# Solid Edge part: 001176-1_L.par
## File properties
Last saved by: morva
Revision: 82
Accuracy: 0.990
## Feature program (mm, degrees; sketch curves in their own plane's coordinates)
body "unnamed Body 1"
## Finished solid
Body 1: solid body, 167 faces, 451 edges, 288 vertices.
  Faces by surface: cylinder 75, plane 50, torus 21, spline 10, cone 7, spun 4
  Edges by curve: line 182, circle 153, spline 65, curve on surface 51
Bounding box of the edges (mm; curved faces can reach further): 94.424 x 55.613 x 60.053, from (457.2918, 400.3153, -108.0376) to (551.716, 455.9287, -47.9843).
Cylindrical faces by radius (mm): R0.2 x12, R1 x3, R2 x17, R2.5 x4, R3 x9, R3.5 x5, R5 x2, R5.5 x2, R6 x8, R8 x2, R10 x5, R11 x3, R12 x1, R17 x2
Conical faces (half-angle, radius in mm at the cone's reference point): 1.3972 deg R6.4993 x1, 1.3972 deg R8.95 x1, 26.5651 deg R11.5 x3, 45 deg R4.5 x2
Toroidal faces (ring radius, tube radius in mm): R2.8 r0.2 x3, R3.2 r0.2 x3, R5 r2 x2, R6 r2 x2, R6.9506 r2 x4, R8 r2 x2, R14 r2 x2, R15 r2 x3
Planar faces by outward normal: oblique 50
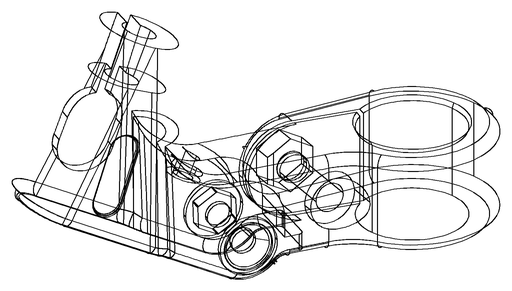
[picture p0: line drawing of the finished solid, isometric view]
